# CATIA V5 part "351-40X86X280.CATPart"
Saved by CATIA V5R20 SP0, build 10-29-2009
Part number: 351-40X86X280
Definition: NONE
Nomenclature: 351-40X86X280
Source: Unknown
Description: 351-40X86X280
Bounding box of the stored display mesh (mm): x -8 to 272, y -26 to 26, z -26 to 26
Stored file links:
  C:\Users\Utente\Desktop\IO LAVORO\3D X SITO CF\X SITO\PLASTICA\351\351-40X86X280.CATPart

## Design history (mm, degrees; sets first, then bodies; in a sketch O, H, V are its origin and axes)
Body1 "351-40X86X280" (main body)
  Solid1: solid without history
